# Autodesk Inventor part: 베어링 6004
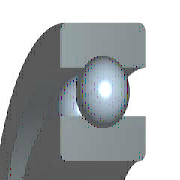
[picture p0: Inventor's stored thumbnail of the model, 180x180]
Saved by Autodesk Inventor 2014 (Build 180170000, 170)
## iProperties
IsCustomPart: 1
Created: 2012-02
Part Number: 베어링 6004
Material: 강철, 연강
Description: 깊은 그루브 볼 베어링
Document SubType Name: Modeling
Standard: KS B 2023
Designer: mduedu
Standards Organization: KS
Language: ko-KR
Size Designation: 6004 - 20 x 42 x 12
Categories: <MemberInstance><Categories><Category DisplayName="샤프트 부품" InternalName="7f7aeb1f-a693-4053-b835-cee3144e0d98" Mnemonic="SHFT"><Category DisplayName="베어링" Inter
Density: 7.86 g/cm^3
Appearance: 노란색
Mass: 61.3817 g
Surface Area: 70.0178 cm^2
Volume: 7.80938 cm^3
Author: mduedu
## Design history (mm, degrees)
sketch "스케치" dims "d0" = 5.72 (= -0.26 x WD + 0.26 x BD)
  geometry: L1 (3.14, 15.5)-(8.86, 15.5); L2 (6, 15.5)-(6, 12.64); L3 (6, 15.5)-(6, 18.36); L4 (3.875, 13.586)-(0, 13.586); L5 (0, 10)-(12, 10); L6 (3.875, 17.414)-(0, 17.414); L7 (0, 21)-(12, 21); L8 (12, 10)-(12, 13.586); L9 (8.125, 13.586)-(12, 13.586); L10 (8.125, 17.414)-(12, 17.414); L11 (12, 21)-(12, 17.414); L12 (-1.4, 0)-(8.4, 0) reference; L13 (0, -0.3)-(0, 5.3) reference
  constraints: 22 end point, 4 point on line, 2 collinear, 2 perpendicular, 2 symmetric about line, 1 midpoint, 1 parallel, 14 other
  dimensions: "d9" = 20 diameter of L5 L12 (= WD); "d11" = 42 diameter of L7 L12 (= BD); "d12" = 12 distance between parallel lines of L8 L13 (= KB); "d13" = 27.172 diameter of L9 L12 (= 0.326 x BD + 0.674 x WD)
revolve "본체" stored, may be unused: angle "d6" = 90 deg
revolve "볼" stored, may be unused: angle "d7" = 90 deg
pattern_circular "IDS_ARRAYBALL[SIMPL:T]" dims angle "d3" = 360 deg
body "Solid1"
fillet "모깎기1" dims "d1" = 0.6 (= KRS)
other parameters: "WD" = 20 [user parameter; used in 5 equation terms], "BD" = 42 [user parameter; used in 5 equation terms], "KB" = 12 [user parameter; used in 1 equation term], "KRS" = 0.6 [user parameter; used in 1 equation term], "d4" = 0, "d5" = 0, "d8" = 0, "d14" = 0, "d15" = 0, "BBA" = 0 [user parameter], "BC0" = 5000000 [user parameter], "BC" = 9360000 [user parameter], "BR" = 21 (= 0.5 x BD) [user parameter]
